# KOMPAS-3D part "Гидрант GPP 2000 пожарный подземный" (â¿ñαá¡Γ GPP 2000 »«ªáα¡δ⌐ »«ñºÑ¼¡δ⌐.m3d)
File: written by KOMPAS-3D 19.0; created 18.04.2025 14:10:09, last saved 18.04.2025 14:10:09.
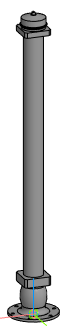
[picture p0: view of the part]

Document properties: Полное имя файла: E:\Dendor Работа Сачек\3D для проекитирвщиков\11.1 Тип GPP. Гидрант пожарный подземный\stp_Тип GPP. 750-6000 Гидрант пожарный подземный\Гидрант GPP 2000 пожарный подземный.m3d

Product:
- Part/product: Гидрант GPP 2000 пожарный подземный

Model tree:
1. Операция без истории:1  (labels: Гидрант GPP 2000 пожарный подземный)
